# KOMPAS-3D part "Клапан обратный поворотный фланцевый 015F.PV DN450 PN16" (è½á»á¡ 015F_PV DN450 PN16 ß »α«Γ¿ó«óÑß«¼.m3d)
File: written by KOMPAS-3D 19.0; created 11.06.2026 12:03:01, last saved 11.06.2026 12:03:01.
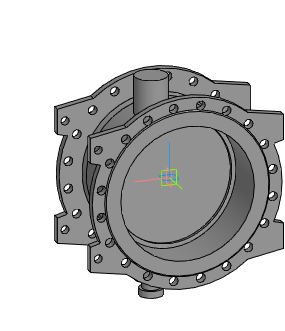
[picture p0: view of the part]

Document properties: Автор: Энергия; Полное имя файла: Z:\3.Личные\kachalov\001_3d для проектировщиков\5.5 Тип 015F.PV Клапан обратный поворотный с двумя эксцентриками\_stp_Клапан 015F.PV DN300-DN1200 с противовесом\Клапан 015F_PV DN450 PN16 с противовесом.m3d

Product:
- Part/product: Клапан обратный поворотный фланцевый 015F.PV DN450 PN16

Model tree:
1. Операция без истории:1
2. Сплайн:1
     Координата Y = 30; Координата Z = 225; Вес = 1; Координата X = 450; Координата Y = 89.2436; Координата Z = 225; Вес = 0.333333; Координата X = 450; Координата Y = 89.2436; Координата Z = -225; Вес = 0.333333; Координата Y = 30; Координата Z = -225; Вес = 1; Координата X = -450; Координата Y = -29.2436; Координата Z = -225; Вес = 0.333333; Координата X = -450; Координата Y = -29.2436; Координата Z = 225; Вес = 0.333333; Порядок = 4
